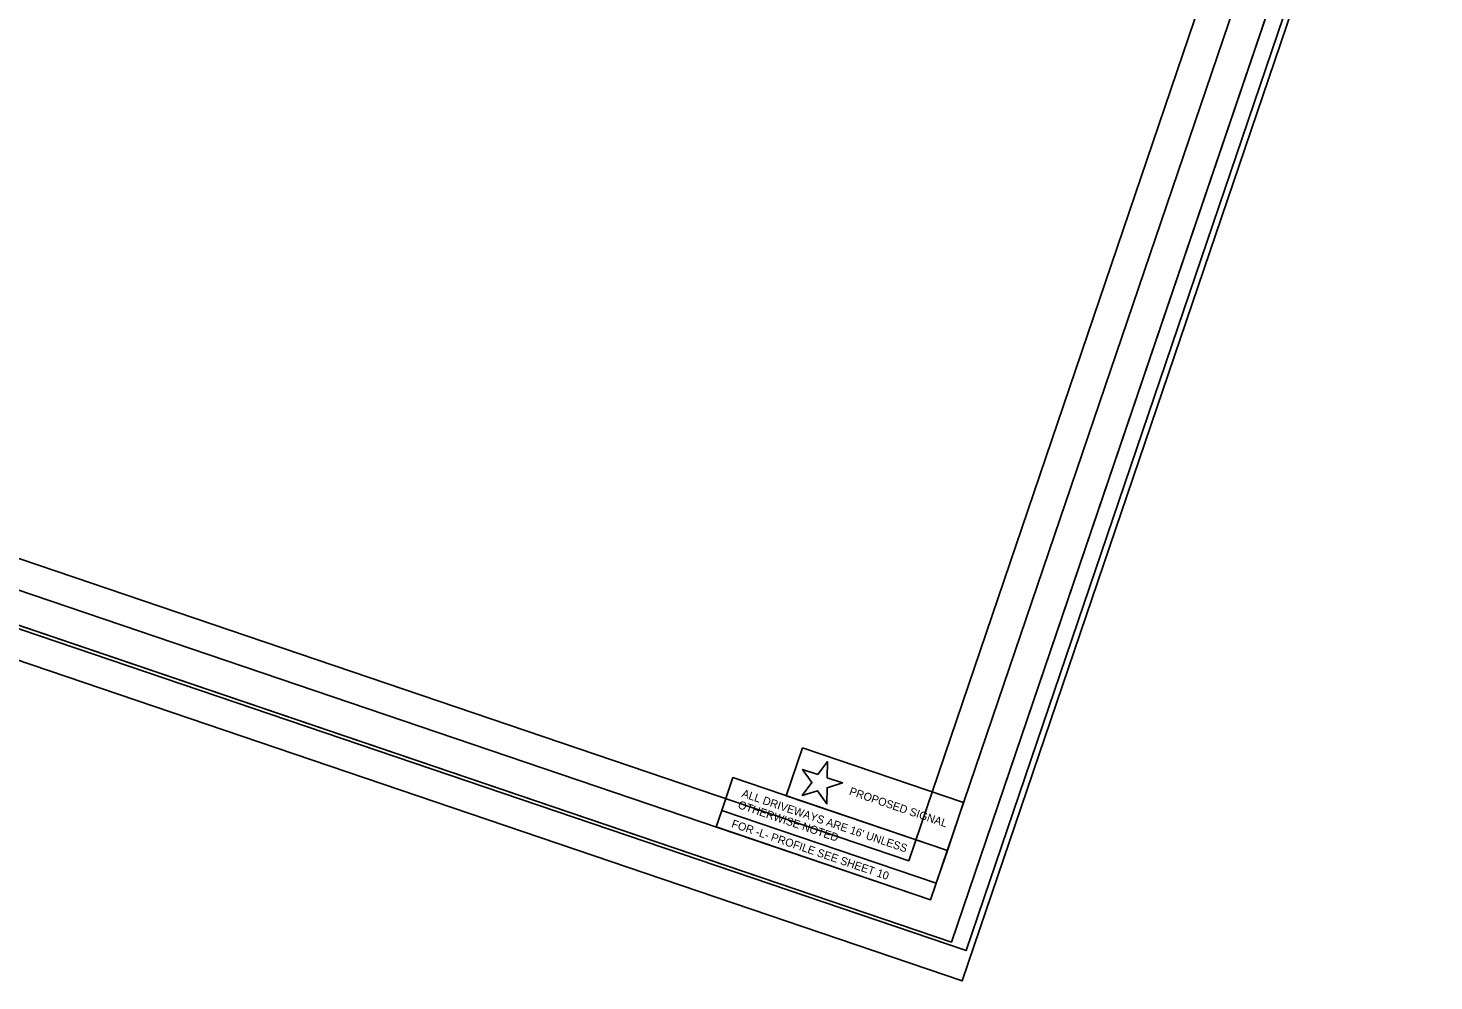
# Model space of a CAD drawing. Extents: x 2298691 to 2299860, y 598939 to 599889.
# Drawn here: x 2299227 to 2299860, y 598939 to 599368 of the extents above; entities that cross this region are included whole.
import ezdxf

# ---------------------------------------------------------------- set-up
doc = ezdxf.new("R2010")
doc.units = 0
for name, color, linetype in [('Default', 7, 'Continuous'), ('Prop DSN Text', 7, 'Continuous'), ('Prop PFL Text', 7, 'Continuous'), ('Prop RDY Traffic Signal CELL', 7, 'Continuous'), ('Scratch_Level_0', 7, 'Continuous'), ('Sheet Border Standard 30in CELL', 7, 'Continuous'), ('Sheet Layout Plan Border', 7, 'Continuous'), ('Sheet Plan Layout CELL', 7, 'Continuous'), ('Sheet Plot Border Inside CELL', 7, 'Continuous'), ('Sheet Plot Border Outside CELL', 7, 'Continuous')]:
    doc.layers.add(name, color=color, linetype=linetype)

msp = doc.modelspace()

# ---------------------------------------------------------------- linework, layer by layer
at = {"layer": 'Default'}
msp.add_lwpolyline([(2299575.52, 599043.96), (2299648.09, 599019.32), (2299640.77, 598997.78), (2299568.21, 599022.43)], close=True, dxfattribs=at)
at = {"layer": 'Prop PFL Text'}
for points in [[(2299539.21, 599015.8), (2299635.75, 598983.01), (2299640.77, 598997.78), (2299544.23, 599030.58)], [(2299536.7, 599008.41), (2299633.24, 598975.62), (2299635.75, 598983.01), (2299539.21, 599015.8)]]:
    msp.add_lwpolyline(points, close=True, dxfattribs=at)
at = {"layer": 'Prop RDY Traffic Signal CELL'}
msp.add_lwpolyline([(2299582.48, 599031.95), (2299575.61, 599034.28), (2299579.79, 599028.36), (2299575.44, 599022.53), (2299582.39, 599024.69), (2299586.58, 599018.76), (2299586.67, 599026.02), (2299593.61, 599028.17), (2299586.73, 599030.51), (2299586.83, 599037.78), (2299582.48, 599031.95)], dxfattribs=at)
at = {"layer": 'Scratch_Level_0'}
msp.add_lwpolyline([(2299002.4, 599823.52), (2298809.46, 599255.41), (2299633.24, 598975.62), (2299795.1, 599452.24), (2299681.46, 599490.84), (2299712.53, 599582.33)], close=True, dxfattribs=at)
at = {"layer": 'Sheet Border Standard 30in CELL'}
msp.add_lwpolyline([(2299845.21, 599553.11), (2298993.02, 599842.55), (2298790.42, 599246.02), (2299642.61, 598956.58)], close=True, dxfattribs=at)
at = {"layer": 'Sheet Layout Plan Border'}
msp.add_lwpolyline([(2299035.49, 599796.46), (2298855.43, 599254), (2299623.37, 598993.18), (2299776.1, 599442.85), (2299690.83, 599471.81), (2299700.48, 599500.22), (2299721.92, 599563.32), (2299035.49, 599796.46)], close=True, dxfattribs=at)
at = {"layer": 'Sheet Plan Layout CELL'}
msp.add_lwpolyline([(2298993.02, 599842.55), (2298790.44, 599246.03), (2299642.62, 598956.59), (2299806.65, 599439.6), (2299693.01, 599478.2), (2299731.56, 599591.71)], close=True, dxfattribs=at)
at = {"layer": 'Sheet Plot Border Inside CELL'}
msp.add_lwpolyline([(2299852.81, 599552.15), (2298906.02, 599873.72), (2298702.43, 599274.29), (2299649.22, 598952.72)], close=True, dxfattribs=at)
at = {"layer": 'Sheet Plot Border Outside CELL'}
msp.add_lwpolyline([(2299859.69, 599564.04), (2298902.97, 599888.98), (2298690.72, 599264.04), (2299647.44, 598939.1)], close=True, dxfattribs=at)

# ---------------------------------------------------------------- texts
at = {"layer": 'Prop DSN Text'}
for s, height, p in [("ALL DRIVEWAYS ARE 16' UNLESS ", 3.6, (2299547.95, 599022.02)), ('PROPOSED SIGNAL', 3.5953, (2299596.31, 599022.99)), ('OTHERWISE NOTED', 3.6, (2299546.22, 599016.91)), ('FOR -L- PROFILE SEE SHEET 10', 3.6, (2299543.32, 599008.38))]:
    msp.add_text(s, height=height, rotation=341.24042, dxfattribs=at).set_placement(p)

doc.saveas('drawing.dxf')
